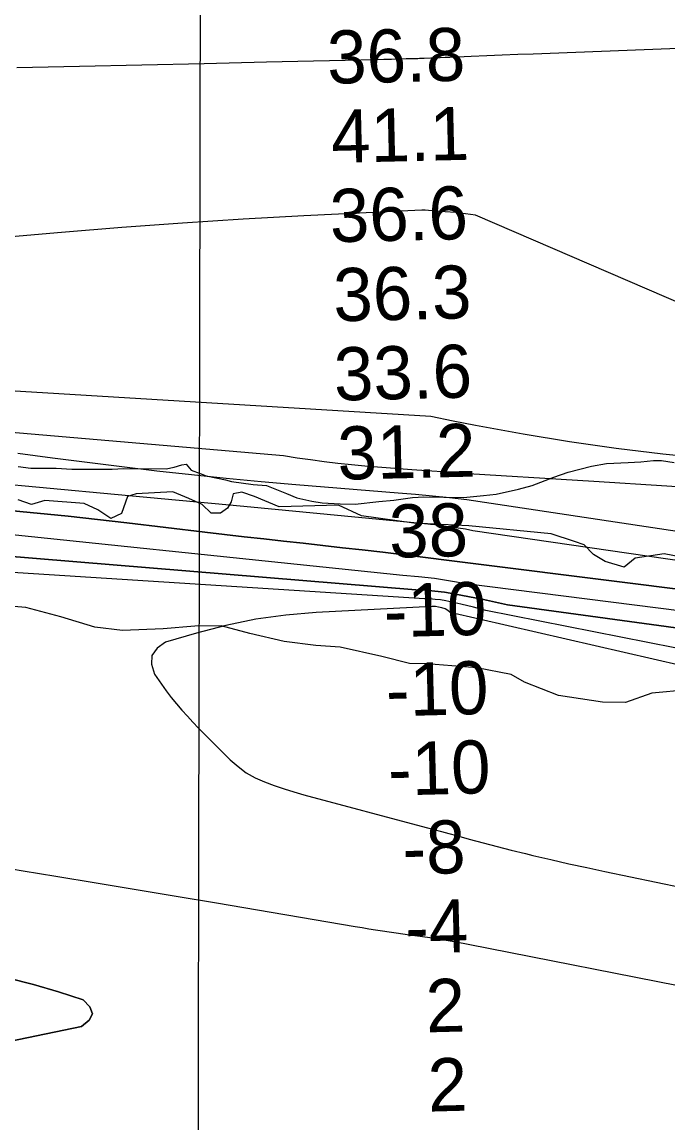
# Model space of a CAD drawing. Extents: x 3192986 to 3230865, y 867483 to 892886.
# Drawn here: x 3207434 to 3208250, y 879965 to 881355 of the extents above; entities that cross this region are included whole.
import ezdxf

# ---------------------------------------------------------------- set-up
doc = ezdxf.new("R2010")
doc.units = 0
for name, color, linetype in [('V-GRID-MAJR', 7, 'Continuous'), ('V-RIVR-EDGE', 7, 'Continuous'), ('V-RIVR-RANG', 7, 'Continuous'), ('V-SITE-VEGE', 7, 'Continuous'), ('V-TOPO-DPTH', 7, 'Continuous'), ('V-TOPO-MAJR', 7, 'Continuous'), ('V-TOPO-MINR', 7, 'Continuous'), ('V-TOPO-WATR', 7, 'Continuous')]:
    doc.layers.add(name, color=color, linetype=linetype)

msp = doc.modelspace()

# ---------------------------------------------------------------- linework, layer by layer
at = {"layer": 'V-GRID-MAJR'}
msp.add_spline([(3207642.5, 872901.1), (3207654.8, 878960.7), (3207667.2, 885023.3), (3207679.5, 891086), (3207679.5, 891089.1)], degree=3, dxfattribs=at)
at = {"layer": 'V-RIVR-EDGE'}
for points in [[(3207833.7, 880745), (3207758.5, 880743), (3207727.7, 880756.1), (3207711.6, 880761.4), (3207700.7, 880759.2), (3207698.1, 880749.2), (3207693.3, 880741), (3207684.6, 880734.9), (3207672.8, 880735), (3207661.6, 880745.9), (3207644.6, 880753.3), (3207624.2, 880761.6), (3207578.1, 880759.1), (3207567.3, 880756.1), (3207559.4, 880734.4), (3207546.3, 880728.3), (3207529.8, 880739.2), (3207512.5, 880747.1), (3207462.9, 880750.7), (3207446, 880746), (3207429, 880751.7)], [(3208284.3, 880676.1), (3208244.8, 880683.6), (3208208.2, 880678), (3208194.3, 880666.7), (3208170.4, 880673.7), (3208155.6, 880682.9), (3208143.5, 880694.7), (3208131.3, 880699.1), (3208102.2, 880708.7), (3207997.9, 880718.9), (3207928.8, 880722.2), (3207862.4, 880731.5), (3207833.7, 880745)]]:
    msp.add_lwpolyline(points, dxfattribs=at)
at = {"layer": 'V-SITE-VEGE'}
for p, q in [((3207429.3, 880793.6), (3207445.3, 880791.7)), ((3207445.3, 880791.7), (3207477.3, 880791.6)), ((3207477.3, 880791.6), (3207497.1, 880790.5)), ((3207497.1, 880790.5), (3207509.3, 880790.5)), ((3207509.3, 880790.5), (3207515.9, 880790.5)), ((3207515.9, 880790.5), (3207548, 880790.3)), ((3207548, 880790.3), (3207562.1, 880791.2)), ((3207562.1, 880791.2), (3207615.8, 880791)), ((3207615.8, 880791), (3207626.2, 880792.9)), ((3207626.2, 880792.9), (3207635.6, 880795.7)), ((3207635.6, 880795.7), (3207641.3, 880796.6)), ((3207641.3, 880796.6), (3207647.7, 880789)), ((3207647.7, 880789), (3207659, 880785)), ((3208123.5, 880786.8), (3208152.9, 880794)), ((3208152.9, 880794), (3208171.8, 880797.4)), ((3208171.8, 880797.4), (3208199.1, 880798.9)), ((3208199.1, 880798.9), (3208215.1, 880799.7)), ((3208215.1, 880799.7), (3208231.2, 880801.3)), ((3208231.2, 880801.3), (3208241.5, 880801.2)), ((3208241.5, 880801.2), (3208257.5, 880799)), ((3207659, 880785), (3207666.5, 880782.1)), ((3207666.5, 880782.1), (3207690.9, 880777)), ((3207690.9, 880777), (3207698.4, 880775)), ((3207698.4, 880775), (3207725.7, 880770.9)), ((3208078.1, 880769.6), (3208105.6, 880780.5)), ((3208105.6, 880780.5), (3208123.5, 880786.8)), ((3207725.7, 880770.9), (3207742.6, 880769.7)), ((3207742.6, 880769.7), (3207767.9, 880759.9)), ((3208032.7, 880758.9), (3208061, 880765.1)), ((3208061, 880765.1), (3208078.1, 880769.6)), ((3207767.9, 880759.9), (3207781, 880754.1)), ((3207781, 880754.1), (3207799.8, 880750)), ((3207799.8, 880750), (3207813, 880747.9)), ((3207813, 880747.9), (3207835.6, 880746.7)), ((3207854.4, 880746.4), (3207884.6, 880749.7)), ((3207884.6, 880749.7), (3207903.5, 880751.4)), ((3207903.5, 880751.4), (3207927.1, 880754.8)), ((3207927.1, 880754.8), (3207941.2, 880755.5)), ((3207941.2, 880755.5), (3207991.2, 880754.8)), ((3207991.2, 880754.8), (3208016.6, 880757.3)), ((3208016.6, 880757.3), (3208032.7, 880758.9)), ((3207835.6, 880746.7), (3207854.4, 880746.4)), ((3207438.7, 880615.9), (3207403, 880618.9)), ((3207482.9, 880604.2), (3207438.7, 880615.9)), ((3207526.1, 880590.8), (3207482.9, 880604.2)), ((3207560.9, 880586.9), (3207526.1, 880590.8)), ((3207612.1, 880588.7), (3207560.9, 880586.9)), ((3207652.1, 880592.4), (3207612.1, 880588.7)), ((3207685.3, 880592.7), (3207652.1, 880592.4)), ((3207721.8, 880582.9), (3207685.3, 880592.7)), ((3207765.1, 880572.9), (3207721.8, 880582.9)), ((3207805.1, 880568), (3207765.1, 880572.9)), ((3207835.7, 880565.9), (3207805.1, 880568)), ((3207888.3, 880554.1), (3207835.7, 880565.9)), ((3207923.1, 880545.1), (3207888.3, 880554.1)), ((3207945.2, 880544.7), (3207923.1, 880545.1)), ((3208008.1, 880539.6), (3207945.2, 880544.7)), ((3208051.5, 880531.3), (3208008.1, 880539.6)), ((3208068.3, 880521.7), (3208051.5, 880531.3)), ((3208111.5, 880504.9), (3208068.3, 880521.7)), ((3208275.1, 880511.9), (3208229.1, 880507.5)), ((3208166.8, 880496.4), (3208111.5, 880504.9)), ((3208229.1, 880507.5), (3208195.7, 880496)), ((3208195.7, 880496), (3208166.8, 880496.4))]:
    msp.add_line(p, q, dxfattribs=at)
at = {"layer": 'V-TOPO-DPTH'}
for points in [[(3209381.7, 880557.6), (3208730.8, 880641.2), (3207995.5, 880751.8), (3207973.9, 880754.2), (3207952.3, 880756.4), (3207930.6, 880758.4), (3207909, 880760.3), (3207779.8, 880770.7), (3207735.8, 880774.5), (3207691.8, 880778.6), (3207647.9, 880783.2), (3207604, 880788.1), (3207560.2, 880793.3), (3207516.3, 880798.7), (3207472.5, 880804.3), (3207428.7, 880810)], [(3207418.1, 880738.3), (3207492.3, 880730.9), (3207566.4, 880722.7), (3207664.9, 880711), (3207689.7, 880708.1), (3207714.5, 880705.2), (3207739.3, 880702.4), (3207764.1, 880699.6), (3207789, 880696.9), (3207813.8, 880694.1), (3207838.6, 880691.3), (3207863.4, 880688.6), (3207889.7, 880685.7), (3208705, 880583.5), (3208707.4, 880583.4), (3208709.8, 880583), (3209077.7, 880436.1)], [(3207418.1, 880738.3), (3207492.3, 880730.9), (3207566.4, 880722.7), (3207664.9, 880711), (3207689.7, 880708.1), (3207714.5, 880705.2), (3207739.3, 880702.4), (3207764.1, 880699.6), (3207789, 880696.9), (3207813.8, 880694.1), (3207838.6, 880691.3), (3207863.4, 880688.6), (3207889.7, 880685.7), (3208705, 880583.5), (3208707.4, 880583.4), (3208709.8, 880583), (3209077.7, 880436.1)], [(3207212.3, 880697.6), (3207931.1, 880638.2), (3207943.2, 880637.6), (3207955.3, 880636.6), (3207967.3, 880635), (3207979.3, 880633), (3208016.5, 880625.7), (3208046.9, 880619.2), (3208700.1, 880529.9), (3208700.6, 880529.9), (3208701.7, 880529.8), (3208703.2, 880529.8), (3208704.2, 880529.6), (3208759.1, 880518.1), (3208763.2, 880517), (3208767, 880515.4), (3208770.7, 880513.4), (3208774.2, 880511), (3208777.6, 880508.5), (3208781.1, 880506.2), (3208784.9, 880504.2), (3209001.4, 880424.6), (3209058.1, 880409.9), (3209115.5, 880397.3)], [(3209115.5, 880397.3), (3209058.1, 880409.9), (3209001.4, 880424.6), (3208784.9, 880504.2), (3208781.1, 880506.2), (3208777.6, 880508.5), (3208774.2, 880511), (3208770.7, 880513.4), (3208767, 880515.4), (3208763.2, 880517), (3208759.1, 880518.1), (3208704.2, 880529.6), (3208703.2, 880529.8), (3208701.7, 880529.8), (3208700.6, 880529.9), (3208700.1, 880529.9), (3208046.9, 880619.2), (3208016.5, 880625.7), (3207979.3, 880633), (3207967.3, 880635), (3207955.3, 880636.6), (3207943.2, 880637.6), (3207931.1, 880638.2), (3207212.3, 880697.6)], [(3208670.2, 880449.4), (3207974.7, 880609.6), (3207971.6, 880612.2), (3207968.1, 880614), (3207964.2, 880615.4), (3207959.8, 880616.4), (3207955.9, 880617), (3207954, 880617.1), (3207952, 880617.1), (3207805.2, 880609.5), (3207766.9, 880606.2), (3207729, 880601), (3207691.5, 880593.2), (3207654.3, 880583.6), (3207615.3, 880572), (3207604.5, 880564.4), (3207597.9, 880555.4), (3207597.5, 880544.3), (3207601.2, 880531.7), (3207610.1, 880518.9), (3207616.2, 880510.5), (3207622.5, 880502.2), (3207629.1, 880494.2), (3207635.8, 880486.3), (3207642.8, 880478.6), (3207649.8, 880470.9), (3207657, 880463.4), (3207664.3, 880456), (3207697, 880423.5), (3207706.7, 880415), (3207717.1, 880407.3), (3207728.3, 880401), (3207740.1, 880395.6), (3207752.4, 880391.1), (3207764.8, 880386.8), (3207777.3, 880383), (3207789.9, 880379.4), (3207944.4, 880338.2), (3207953.9, 880335.6), (3207963.4, 880333.1), (3207972.9, 880330.5), (3207982.4, 880327.9), (3207998.7, 880323.4), (3208016.3, 880318.6), (3208034, 880314), (3208051.7, 880309.5), (3208069.5, 880305.1), (3208079.1, 880302.8), (3208101.8, 880297.5), (3208124.4, 880292.3), (3208147.1, 880287.4), (3208169.9, 880282.5), (3208396.6, 880235.6)], [(3208670.2, 880449.4), (3207974.7, 880609.6), (3207971.6, 880612.2), (3207968.1, 880614), (3207964.2, 880615.4), (3207959.8, 880616.4), (3207955.9, 880617), (3207954, 880617.1), (3207952, 880617.1), (3207805.2, 880609.5), (3207766.9, 880606.2), (3207729, 880601), (3207691.5, 880593.2), (3207654.3, 880583.6), (3207615.3, 880572), (3207604.5, 880564.4), (3207597.9, 880555.4), (3207597.5, 880544.3), (3207601.2, 880531.7), (3207610.1, 880518.9), (3207616.2, 880510.5), (3207622.5, 880502.2), (3207629.1, 880494.2), (3207635.8, 880486.3), (3207642.8, 880478.6), (3207649.8, 880470.9), (3207657, 880463.4), (3207664.3, 880456), (3207697, 880423.5), (3207706.7, 880415), (3207717.1, 880407.3), (3207728.3, 880401), (3207740.1, 880395.6), (3207752.4, 880391.1), (3207764.8, 880386.8), (3207777.3, 880383), (3207789.9, 880379.4), (3207944.4, 880338.2), (3207953.9, 880335.6), (3207963.4, 880333.1), (3207972.9, 880330.5), (3207982.4, 880327.9), (3207998.7, 880323.4), (3208016.3, 880318.6), (3208034, 880314), (3208051.7, 880309.5), (3208069.5, 880305.1), (3208079.1, 880302.8), (3208101.8, 880297.5), (3208124.4, 880292.3), (3208147.1, 880287.4), (3208169.9, 880282.5), (3208396.6, 880235.6)], [(3207046.4, 879991), (3207509.1, 880086.8), (3207518.7, 880094.7), (3207523.1, 880103), (3207519.7, 880111.7), (3207511.1, 880120.7), (3207480, 880130.6), (3207448.7, 880139.8), (3207417.1, 880148)], [(3207046.4, 879991), (3207509.1, 880086.8), (3207518.7, 880094.7), (3207523.1, 880103), (3207519.7, 880111.7), (3207511.1, 880120.7), (3207480, 880130.6), (3207448.7, 880139.8), (3207417.1, 880148)]]:
    msp.add_lwpolyline(points, dxfattribs=at)
at = {"layer": 'V-TOPO-MAJR'}
for points in [[(3207427.6, 881297.5), (3207506.4, 881299.2), (3207585.2, 881301), (3207664, 881302.7), (3207742.7, 881304.5), (3207881.5, 881307.6), (3207890.9, 881307.8), (3207900.3, 881308.1), (3207909.7, 881308.3), (3207919.1, 881308.6), (3207933.9, 881309), (3207935.9, 881309.1), (3207939.8, 881309.2), (3207941.8, 881309.3), (3207950, 881309.6), (3207956.1, 881309.8), (3207962.1, 881310.1), (3207968.2, 881310.3), (3207974.3, 881310.6), (3208001.2, 881311.7), (3208020.7, 881312.5), (3208040.2, 881313.3), (3208059.8, 881314.1), (3208079.3, 881314.9), (3208499.9, 881331)], [(3209436.3, 880669.7), (3208715.8, 880813.8), (3208712.4, 880814.4), (3208708.9, 880814.9), (3208705.4, 880815.5), (3208702, 880816.1), (3208697.3, 880816.9), (3208693.2, 880817.7), (3208689.2, 880818.5), (3208685.2, 880819.4), (3208681.1, 880820.3), (3208006.4, 881111.2), (3207993.8, 881112.8), (3207981.1, 881114.2), (3207968.3, 881115.4), (3207947.1, 881117.1), (3207942.9, 881117.3), (3207938.6, 881117.2), (3207789.7, 881110), (3207713.2, 881105.9), (3207636.7, 881101.1), (3207560.2, 881095.5), (3207483.8, 881089.3), (3207017.8, 881048.8)]]:
    msp.add_lwpolyline(points, dxfattribs=at)
at = {"layer": 'V-TOPO-MINR'}
for points in [[(3209306.6, 880637.1), (3208762.5, 880760), (3208736.6, 880763.6), (3208710.8, 880766.9), (3208684.8, 880769.7), (3208658.9, 880772.3), (3208302.2, 880803.6), (3208243.1, 880809.5), (3208184.2, 880816.5), (3208125.4, 880825.1), (3208066.8, 880834.7), (3208006.5, 880845.4), (3207978.2, 880851), (3207950.1, 880857.1), (3206961.9, 880917.1)], [(3208340.6, 880762.8), (3208248.2, 880768.8), (3208155.9, 880774.7), (3207977.1, 880786), (3207964.3, 880786.9), (3207951.5, 880787.8), (3207938.7, 880788.7), (3207926, 880789.7), (3207867, 880794.3), (3207849.8, 880795.9), (3207832.6, 880797.6), (3207815.5, 880799.7), (3207798.4, 880802), (3207781.3, 880804.5), (3207764.2, 880807.2), (3206989.5, 880873.9)], [(3209381.7, 880557.6), (3208730.8, 880641.2), (3207995.5, 880751.8), (3207973.9, 880754.2), (3207952.3, 880756.4), (3207930.6, 880758.4), (3207909, 880760.3), (3207779.8, 880770.7), (3207735.8, 880774.5), (3207691.8, 880778.6), (3207647.9, 880783.2), (3207604, 880788.1), (3207560.2, 880793.3), (3207516.3, 880798.7), (3207472.5, 880804.3), (3207428.7, 880810)], [(3209137.2, 880433.7), (3208718.6, 880608.5), (3208003, 880712.7), (3207993.8, 880714.5), (3207984.5, 880716.1), (3207960.3, 880719.4), (3207956.8, 880719.9), (3207953.3, 880720.4), (3207949.7, 880720.7), (3207946.2, 880721.1), (3207713.9, 880743.1), (3207632.4, 880750.7), (3207550.9, 880758.4), (3207469.4, 880765.9), (3207387.9, 880773.4)], [(3209092, 880414.1), (3208705.5, 880556.6), (3208701.1, 880556.8), (3208696.6, 880556.8), (3208695.2, 880556.8), (3207994.6, 880645.5), (3207974.8, 880649.2), (3207954.8, 880652.3), (3207934.7, 880654.5), (3207914.6, 880656.2), (3207291.8, 880720.8)], [(3209115.5, 880397.3), (3209058.1, 880409.9), (3209001.4, 880424.6), (3208784.9, 880504.2), (3208781.1, 880506.2), (3208777.6, 880508.5), (3208774.2, 880511), (3208770.7, 880513.4), (3208767, 880515.4), (3208763.2, 880517), (3208759.1, 880518.1), (3208704.2, 880529.6), (3208703.2, 880529.8), (3208701.7, 880529.8), (3208700.6, 880529.9), (3208700.1, 880529.9), (3208046.9, 880619.2), (3208016.5, 880625.7), (3207979.3, 880633), (3207967.3, 880635), (3207955.3, 880636.6), (3207943.2, 880637.6), (3207931.1, 880638.2), (3207212.3, 880697.6)], [(3209400, 880329.4), (3209056.3, 880395.6), (3208996.8, 880407.6), (3208937.4, 880420.4), (3208878.3, 880434.3), (3208819.3, 880448.9), (3208763.3, 880463.4), (3208732.3, 880470.8), (3208701.2, 880477.4), (3208019.6, 880612), (3208003.9, 880616.4), (3207987.9, 880620.2), (3207968.9, 880624.1), (3207962.3, 880625.3), (3207955.6, 880626.1), (3207949, 880626.6), (3207942.2, 880626.8), (3207066.5, 880682.8)], [(3208670.2, 880449.4), (3207974.7, 880609.6), (3207971.6, 880612.2), (3207968.1, 880614), (3207964.2, 880615.4), (3207959.8, 880616.4), (3207955.9, 880617), (3207954, 880617.1), (3207952, 880617.1), (3207805.2, 880609.5), (3207766.9, 880606.2), (3207729, 880601), (3207691.5, 880593.2), (3207654.3, 880583.6), (3207615.3, 880572), (3207604.5, 880564.4), (3207597.9, 880555.4), (3207597.5, 880544.3), (3207601.2, 880531.7), (3207610.1, 880518.9), (3207616.2, 880510.5), (3207622.5, 880502.2), (3207629.1, 880494.2), (3207635.8, 880486.3), (3207642.8, 880478.6), (3207649.8, 880470.9), (3207657, 880463.4), (3207664.3, 880456), (3207697, 880423.5), (3207706.7, 880415), (3207717.1, 880407.3), (3207728.3, 880401), (3207740.1, 880395.6), (3207752.4, 880391.1), (3207764.8, 880386.8), (3207777.3, 880383), (3207789.9, 880379.4), (3207944.4, 880338.2), (3207953.9, 880335.6), (3207963.4, 880333.1), (3207972.9, 880330.5), (3207982.4, 880327.9), (3207998.7, 880323.4), (3208016.3, 880318.6), (3208034, 880314), (3208051.7, 880309.5), (3208069.5, 880305.1), (3208079.1, 880302.8), (3208101.8, 880297.5), (3208124.4, 880292.3), (3208147.1, 880287.4), (3208169.9, 880282.5), (3208396.6, 880235.6)], [(3207405.4, 880288.5), (3207435.4, 880283.4), (3207476.8, 880276.6), (3207527.5, 880268.2), (3207578.2, 880259.8), (3207628.8, 880251.3), (3207679.5, 880242.8), (3207854.8, 880213.1), (3207863.3, 880211.7), (3207871.9, 880210.3), (3207880.4, 880209), (3207889, 880207.7), (3207897.6, 880206.4), (3207906.2, 880205.1), (3207914.8, 880203.9), (3207923.4, 880202.8), (3207936.6, 880201), (3207951.7, 880198.8), (3207966.9, 880196.4), (3207982, 880193.8), (3207997.1, 880191), (3208288.1, 880133.7)], [(3207417.1, 880148), (3207448.7, 880139.8), (3207480, 880130.6), (3207511.1, 880120.7), (3207519.7, 880111.7), (3207523.1, 880103), (3207518.7, 880094.7), (3207509.1, 880086.8), (3207046.4, 879991)]]:
    msp.add_lwpolyline(points, dxfattribs=at)
at = {"layer": 'V-TOPO-WATR'}
msp.add_lwpolyline([(3209077.7, 880436.1), (3208709.8, 880583), (3208707.4, 880583.4), (3208705, 880583.5), (3207889.7, 880685.7), (3207863.4, 880688.6), (3207838.6, 880691.3), (3207813.8, 880694.1), (3207789, 880696.9), (3207764.1, 880699.6), (3207739.3, 880702.4), (3207714.5, 880705.2), (3207689.7, 880708.1), (3207664.9, 880711), (3207566.4, 880722.7), (3207492.3, 880730.9), (3207418.1, 880738.3)], dxfattribs=at)

# ---------------------------------------------------------------- texts
at = {"layer": 'V-RIVR-RANG'}
for s, rotation, p in [('36.8', 1.3583, (3207819.9, 881276.8)), ('41.1', 1.3583, (3207824.9, 881176.9)), ('36.6', 1.3583, (3207823.3, 881076.8)), ('36.3', 1.3583, (3207827.7, 880976.9)), ('33.6', 1.3583, (3207828.5, 880876.9)), ('31.2', 1.3583, (3207833, 880777)), ('38', 1.3583, (3207898.1, 880678.5)), ('-10', 1.5181, (3207891.6, 880578.1)), ('-10', 1.5181, (3207894.2, 880478.2)), ('-10', 1.5181, (3207896.8, 880378.2)), ('-8', 1.5181, (3207915, 880278.6)), ('-4', 1.5181, (3207918.4, 880178.7)), ('2', 1.5181, (3207944.5, 880079.4)), ('2', 1.5181, (3207947.1, 879979.4))]:
    msp.add_text(s, height=67, rotation=rotation, dxfattribs=at).set_placement(p)

doc.saveas('drawing.dxf')
